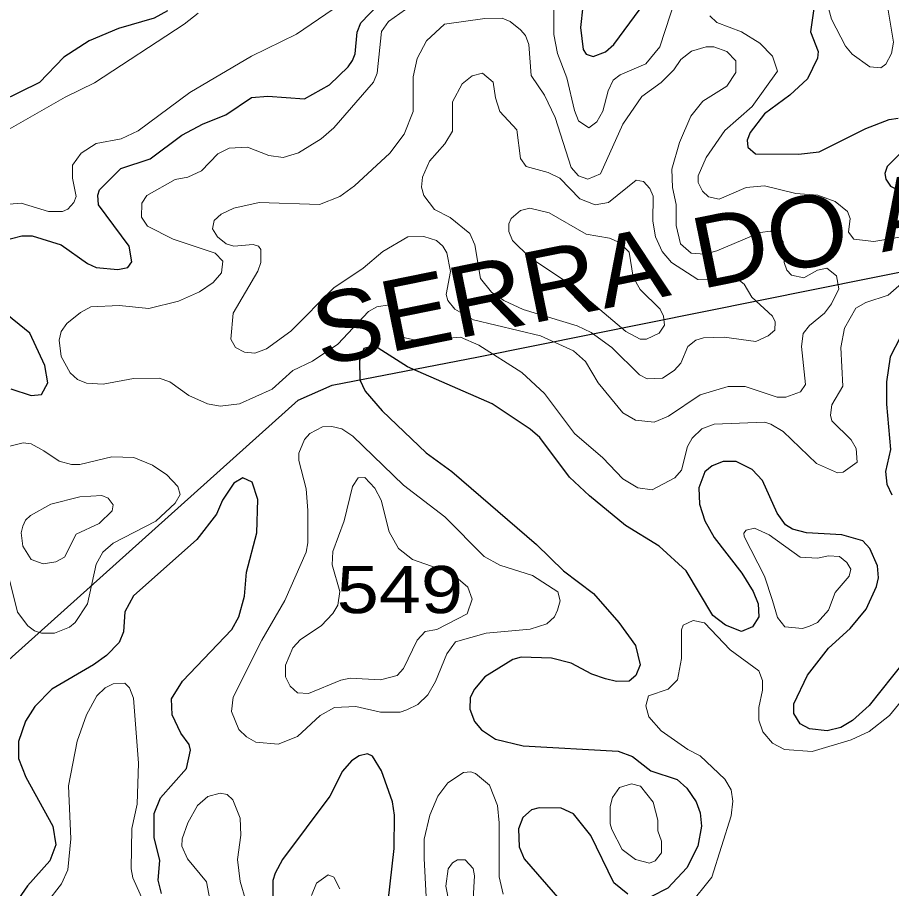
# Model space of a CAD drawing. Extents: x 577 to 602.9, y 7483.8 to 7511.6.
# Drawn here: x 597.148 to 598.63, y 7494.897 to 7496.373 of the extents above; entities that cross this region are included whole.
import ezdxf
from ezdxf.enums import TextEntityAlignment as Align

# ---------------------------------------------------------------- set-up
doc = ezdxf.new("R2010")
doc.units = 0
doc.header["$LTSCALE"] = 0.032
for name, color, linetype, lineweight in [('1', 7, 'Continuous', 25), ('2', 7, 'Continuous', 13), ('26', 7, 'Continuous', 25)]:
    doc.layers.add(name, color=color, linetype=linetype, lineweight=lineweight)
doc.layers.add('61', color=7, linetype='Continuous')

msp = doc.modelspace()

# ---------------------------------------------------------------- linework, layer by layer
at = {"layer": '1'}
for points in [[(598.1106, 7496.4294), (598.1026, 7496.3563), (598.1074, 7496.3189), (598.1122, 7496.311), (598.1241, 7496.307), (598.1448, 7496.3149), (598.1591, 7496.3277), (598.2036, 7496.3881)], [(597.1206, 7495.9945), (597.1556, 7496.0032), (597.1731, 7496.0032), (597.2224, 7495.9881), (597.2669, 7495.9563), (597.282, 7495.9499), (597.3186, 7495.946), (597.3353, 7495.9499), (597.3424, 7495.9595), (597.3377, 7495.9857), (597.286, 7496.0557), (597.2844, 7496.0724), (597.2876, 7496.0811), (597.3234, 7496.1177), (597.3735, 7496.1336), (597.4267, 7496.1742), (597.4633, 7496.1933), (597.5015, 7496.2084), (597.5452, 7496.2378), (597.573, 7496.2402), (597.6351, 7496.2354), (597.6772, 7496.2593), (597.709, 7496.2895), (597.7162, 7496.3006), (597.721, 7496.3117), (597.7241, 7496.3483), (597.7305, 7496.3642), (597.7758, 7496.4119)], [(598.4994, 7496.3968), (598.4923, 7496.3491), (598.5058, 7496.3157), (598.5042, 7496.3046), (598.4875, 7496.2696), (598.4573, 7496.2418), (598.4143, 7496.21), (598.3905, 7496.1782), (598.3849, 7496.1654), (598.3865, 7496.1535), (598.3992, 7496.1424), (598.4724, 7496.1416), (598.5074, 7496.1456), (598.5861, 7496.1853), (598.6259, 7496.2004), (598.641, 7496.2028)], [(597.4029, 7496.3849), (597.3798, 7496.3722), (597.3194, 7496.3547), (597.2701, 7496.334), (597.2271, 7496.3062), (597.1858, 7496.2632), (597.0864, 7496.2147)], [(598.6497, 7496.1479), (598.6227, 7496.1209), (598.6187, 7496.109), (598.6203, 7496.0994), (598.6282, 7496.0875), (598.6457, 7496.0788)], [(597.1373, 7495.744), (597.1715, 7495.7329), (597.189, 7495.7344), (597.2001, 7495.7543), (597.1945, 7495.7838), (597.1691, 7495.8386), (597.1214, 7495.8776)], [(598.6449, 7495.8323), (598.6275, 7495.7981), (598.6211, 7495.7559), (598.6211, 7495.7178), (598.6282, 7495.6414), (598.6195, 7495.604), (598.6219, 7495.5826), (598.6306, 7495.5643)], [(598.5209, 7495.1643), (598.4907, 7495.1675), (598.4748, 7495.1762), (598.4644, 7495.1937), (598.4644, 7495.2104), (598.4875, 7495.2589), (598.5233, 7495.3043), (598.5599, 7495.3377), (598.5869, 7495.3703), (598.6044, 7495.4092), (598.6076, 7495.4235), (598.606, 7495.4442), (598.5933, 7495.4736), (598.5813, 7495.4864), (598.5455, 7495.4967), (598.4859, 7495.4999), (598.4621, 7495.5062), (598.4501, 7495.5134), (598.4358, 7495.5333), (598.4112, 7495.5889), (598.3937, 7495.6072), (598.3666, 7495.6207), (598.3444, 7495.6207), (598.3261, 7495.6136), (598.3134, 7495.6032), (598.303, 7495.5762), (598.3046, 7495.5484), (598.3134, 7495.5205), (598.3293, 7495.4919), (598.3762, 7495.4315), (598.3953, 7495.4005), (598.404, 7495.3798), (598.4048, 7495.3575), (598.3945, 7495.3408), (598.3754, 7495.3329), (598.3483, 7495.3432), (598.3269, 7495.3599), (598.2816, 7495.4355), (598.2362, 7495.4776), (598.179, 7495.5126), (598.1177, 7495.5627), (598.0843, 7495.5945), (598.0335, 7495.6613), (598.0176, 7495.6756), (597.9531, 7495.7185), (597.8092, 7495.7814), (597.7599, 7495.8132), (597.7488, 7495.8156), (597.7353, 7495.8124), (597.7281, 7495.7917), (597.7289, 7495.7591), (597.7377, 7495.74), (597.7663, 7495.7066), (597.841, 7495.6358), (597.8848, 7495.604), (598.0279, 7495.48), (598.074, 7495.4355), (598.1249, 7495.3973), (598.1678, 7495.348), (598.1957, 7495.309), (598.2036, 7495.2764), (598.1965, 7495.2581), (598.1853, 7495.2486), (598.1639, 7495.2478), (598.1448, 7495.2526), (598.1217, 7495.2605), (598.0867, 7495.2788), (598.0533, 7495.2876), (598.0024, 7495.2892), (597.9881, 7495.2852), (597.9404, 7495.2558), (597.9229, 7495.2351), (597.9158, 7495.2208), (597.915, 7495.2009), (597.9229, 7495.1802), (597.9349, 7495.1659), (597.9587, 7495.15), (598.0056, 7495.1389), (598.1663, 7495.1301), (598.1909, 7495.1206), (598.2219, 7495.0967), (598.2664, 7495.0816), (598.2831, 7495.0673), (598.299, 7495.0442), (598.3054, 7495.0252), (598.3078, 7495.0029), (598.3014, 7494.9687), (598.2831, 7494.9321), (598.2505, 7494.8979), (598.2219, 7494.8828)], [(597.3925, 7494.8884), (597.387, 7494.9114), (597.3894, 7494.9448), (597.3798, 7494.9838), (597.3798, 7495.0244), (597.391, 7495.0506), (597.4347, 7495.1007), (597.4418, 7495.1317), (597.4395, 7495.1412), (597.4251, 7495.1603), (597.4108, 7495.1913), (597.4092, 7495.2184), (597.4283, 7495.2486), (597.5118, 7495.3361), (597.5237, 7495.3575), (597.5333, 7495.3925), (597.5365, 7495.4331), (597.554, 7495.4999), (597.5556, 7495.5563), (597.546, 7495.5858), (597.5301, 7495.5929), (597.515, 7495.5842), (597.4959, 7495.5555), (597.4856, 7495.5317), (597.4522, 7495.4887), (597.3448, 7495.3933), (597.3305, 7495.3663), (597.3281, 7495.3321), (597.321, 7495.3138), (597.2995, 7495.2923), (597.2772, 7495.2764), (597.2065, 7495.2351), (597.1778, 7495.2057), (597.1619, 7495.181), (597.15, 7495.146), (597.15, 7495.1174), (597.1627, 7495.0856), (597.2081, 7495.0029), (597.2136, 7494.9711), (597.2033, 7494.944), (597.1651, 7494.9019), (597.15, 7494.8796)], [(598.6712, 7495.3066), (598.5917, 7495.2072), (598.5638, 7495.1818), (598.544, 7495.1699), (598.5209, 7495.1643)], [(597.7734, 7494.8454), (597.787, 7494.9647), (597.7877, 7495.0212), (597.7838, 7495.0442), (597.7655, 7495.0967), (597.7504, 7495.1214), (597.7416, 7495.1253), (597.7273, 7495.1222), (597.7146, 7495.1134), (597.6995, 7495.0959), (597.678, 7495.0538), (597.5977, 7494.9464), (597.585, 7494.9234), (597.581, 7494.9106), (597.581, 7494.8749)], [(598.1829, 7494.8876), (598.1591, 7494.9067), (598.1201, 7494.987), (598.0907, 7495.0236), (598.07, 7495.0331), (598.0327, 7495.0339), (598.0199, 7495.0307), (598.0048, 7495.0172), (597.9977, 7494.9981), (597.9985, 7494.9679)], [(597.9985, 7494.9679), (598.0072, 7494.9472), (598.0676, 7494.878)]]:
    msp.add_lwpolyline(points, dxfattribs=at)
at = {"layer": '2'}
for points in [[(598.5145, 7496.4207), (598.5281, 7496.3706), (598.5519, 7496.3245), (598.563, 7496.311), (598.5933, 7496.2895), (598.6115, 7496.2879), (598.6203, 7496.2943), (598.6298, 7496.3125), (598.633, 7496.3316), (598.6243, 7496.3857)], [(598.0573, 7496.4048), (598.0573, 7496.3443), (598.0637, 7496.3125), (598.0796, 7496.2712), (598.0923, 7496.2155), (598.0995, 7496.198), (598.1169, 7496.1861), (598.1305, 7496.1964), (598.1408, 7496.2147), (598.1496, 7496.2489), (598.1583, 7496.2672), (598.1702, 7496.276), (598.2132, 7496.295), (598.237, 7496.3237), (598.2641, 7496.4072)], [(597.4832, 7495.9738), (597.4124, 7495.9977), (597.3687, 7496.0199), (597.3584, 7496.035), (597.3591, 7496.0589), (597.3679, 7496.0716), (597.4156, 7496.0986), (597.4371, 7496.1026), (597.4601, 7496.1137), (597.488, 7496.1424), (597.507, 7496.1519), (597.5381, 7496.1535), (597.5746, 7496.1392), (597.5985, 7496.136), (597.6247, 7496.144), (597.6629, 7496.1678), (597.6844, 7496.1861), (597.752, 7496.264), (597.7583, 7496.2791), (597.7655, 7496.3499), (597.7774, 7496.3666), (597.8156, 7496.3937)], [(597.4546, 7496.3809), (597.4307, 7496.3618), (597.2788, 7496.2624), (597.2295, 7496.2386), (597.1262, 7496.1797)], [(597.1278, 7496.0565), (597.1548, 7496.0589), (597.2009, 7496.0446), (597.2248, 7496.0446), (597.2335, 7496.0485), (597.2438, 7496.0597), (597.2478, 7496.07), (597.2415, 7496.101), (597.2415, 7496.1233), (597.2566, 7496.1432), (597.282, 7496.1599), (597.3242, 7496.1678), (597.3528, 7496.1813), (597.4403, 7496.2465), (597.5452, 7496.3078), (597.6216, 7496.3451), (597.6836, 7496.3873)], [(598.3221, 7496.3762), (598.334, 7496.365), (598.3754, 7496.3491), (598.4064, 7496.33), (598.4279, 7496.3078), (598.4366, 7496.2823), (598.3937, 7496.2227), (598.3476, 7496.1821), (598.3157, 7496.136), (598.3022, 7496.105), (598.3022, 7496.0939), (598.3094, 7496.0788), (598.3197, 7496.0692), (598.338, 7496.0652), (598.3833, 7496.0851), (598.4143, 7496.0883), (598.4676, 7496.0748), (598.505, 7496.0724), (598.5344, 7496.0613), (598.5551, 7496.0446), (598.5599, 7496.0326), (598.5567, 7496.0096), (598.5662, 7495.9977), (598.5996, 7495.9937), (598.6434, 7496.0008)], [(598.1368, 7496.1082), (598.1154, 7496.0994), (598.0995, 7496.105), (598.0867, 7496.1193), (598.0597, 7496.2036), (598.0414, 7496.2418), (598.0191, 7496.2752), (598.0152, 7496.3277), (598.0096, 7496.3428), (598.0009, 7496.3523), (597.9834, 7496.3666), (597.9698, 7496.3722), (597.9404, 7496.3714), (597.872, 7496.3618), (597.8418, 7496.334), (597.8259, 7496.3038), (597.8188, 7496.2728), (597.8188, 7496.2139), (597.8037, 7496.1758), (597.7798, 7496.1432), (597.7194, 7496.0883), (597.6947, 7496.07), (597.6605, 7496.0565), (597.5579, 7496.0597), (597.515, 7496.0501), (597.4935, 7496.0398), (597.4816, 7496.0295), (597.4792, 7496.0151), (597.4872, 7496.0016), (597.5023, 7495.9897), (597.515, 7495.9857), (597.5476, 7495.9889), (597.5571, 7495.9857), (597.5611, 7495.9802), (597.5611, 7495.9579), (597.5556, 7495.9436), (597.5142, 7495.872), (597.5102, 7495.8283), (597.5182, 7495.814), (597.5333, 7495.806), (597.5508, 7495.8044), (597.5707, 7495.8116), (597.612, 7495.8418), (597.6844, 7495.915), (597.7345, 7495.9484), (597.7679, 7495.977), (597.81, 7496.0016), (597.837, 7496.0024), (597.8585, 7495.9953), (597.8696, 7495.9857), (597.876, 7495.9746), (597.8824, 7495.9428), (597.8752, 7495.9038), (597.8776, 7495.8935), (597.8895, 7495.8792), (597.9213, 7495.8609), (598.035, 7495.8338), (598.0907, 7495.8084), (598.1114, 7495.7901), (598.1329, 7495.7543), (598.1742, 7495.7034), (598.1957, 7495.6907), (598.2275, 7495.6875), (598.2521, 7495.6979), (598.3054, 7495.7337), (598.3531, 7495.748), (598.3817, 7495.748), (598.4358, 7495.7297), (598.4509, 7495.7297), (598.4756, 7495.7392), (598.4843, 7495.7511), (598.4772, 7495.8156), (598.4803, 7495.8378), (598.4907, 7495.8513), (598.5161, 7495.872), (598.5281, 7495.8879), (598.5408, 7495.9134), (598.5368, 7495.9356), (598.5201, 7495.9484), (598.5042, 7495.9452), (598.4811, 7495.9324), (598.4605, 7495.9364), (598.4525, 7495.9452), (598.4477, 7495.9579), (598.4462, 7495.9929), (598.4382, 7496.0032), (598.4247, 7496.0112), (598.4072, 7496.0088), (598.334, 7495.9778), (598.3134, 7495.9722), (598.2903, 7495.9738), (598.272, 7495.9897), (598.2649, 7496.0207), (598.2649, 7496.0565), (598.2585, 7496.0851), (598.2577, 7496.1161), (598.2704, 7496.1615), (598.2895, 7496.206), (598.3102, 7496.2314), (598.3507, 7496.2569), (598.3658, 7496.2799)], [(598.3658, 7496.2799), (598.3658, 7496.2998), (598.3507, 7496.3157), (598.3285, 7496.3237), (598.3157, 7496.3237), (598.2911, 7496.3165), (598.2728, 7496.3022), (598.2609, 7496.2847), (598.2394, 7496.2632), (598.2068, 7496.2394), (598.1742, 7496.1925), (598.1368, 7496.1082)], [(598.5265, 7495.6995), (598.5289, 7495.6899), (598.5615, 7495.6573), (598.5702, 7495.643), (598.5718, 7495.6199), (598.5479, 7495.6025), (598.5384, 7495.6017), (598.5026, 7495.6176), (598.4462, 7495.6716), (598.4255, 7495.6844), (598.4151, 7495.6875), (598.3293, 7495.6844), (598.3086, 7495.6764), (598.2919, 7495.6605), (598.2839, 7495.6462), (598.2736, 7495.6064), (598.2625, 7495.5929), (598.2243, 7495.573), (598.1996, 7495.5762), (598.1742, 7495.5913), (598.1408, 7495.6271), (598.0923, 7495.6684), (598.0414, 7495.736), (598.0032, 7495.7718), (597.9301, 7495.8179), (597.8991, 7495.8315), (597.8283, 7495.8251), (597.8005, 7495.8315), (597.7877, 7495.8426), (597.787, 7495.8776), (597.7782, 7495.8863), (597.7575, 7495.8831), (597.7432, 7495.8752), (597.6915, 7495.8195), (597.6486, 7495.7909), (597.6152, 7495.775), (597.5802, 7495.7432), (597.5245, 7495.7185), (597.4919, 7495.7146), (597.4705, 7495.7185), (597.4387, 7495.7329), (597.4069, 7495.7559), (597.3886, 7495.7623), (597.3448, 7495.7615), (597.2939, 7495.7519), (597.2653, 7495.7535), (597.2502, 7495.7599), (597.2375, 7495.771), (597.2224, 7495.7989), (597.2192, 7495.8267), (597.2224, 7495.841), (597.2319, 7495.8545), (597.255, 7495.8736), (597.2725, 7495.8831), (597.321, 7495.8855), (597.3711, 7495.88), (597.4212, 7495.8927), (597.457, 7495.9086), (597.48, 7495.9245), (597.4943, 7495.9404), (597.4967, 7495.9603), (597.4832, 7495.9738)], [(598.6656, 7495.9388), (598.6243, 7495.903), (598.5861, 7495.8903), (598.5694, 7495.8808), (598.5503, 7495.8466), (598.544, 7495.814), (598.5471, 7495.7488), (598.5289, 7495.717), (598.5265, 7495.6995)], [(597.1357, 7495.647), (597.158, 7495.6525), (597.1715, 7495.651), (597.193, 7495.639), (597.2192, 7495.6215), (597.2399, 7495.616), (597.2542, 7495.616), (597.3083, 7495.6287), (597.3456, 7495.6279), (597.3774, 7495.6144), (597.4013, 7495.5985), (597.4204, 7495.5786), (597.4244, 7495.5651), (597.4156, 7495.55), (597.383, 7495.5198), (597.3106, 7495.4824), (597.2931, 7495.4673), (597.282, 7495.4466), (597.2669, 7495.3798), (597.2462, 7495.348), (597.2367, 7495.34), (597.2112, 7495.3297), (597.189, 7495.3297), (597.1771, 7495.3337), (597.1659, 7495.3424), (597.1484, 7495.3655), (597.1341, 7495.4227)], [(598.6672, 7495.2398), (598.6267, 7495.1905), (598.5917, 7495.1635), (598.5615, 7495.1492), (598.4955, 7495.1293), (598.4485, 7495.1325), (598.4279, 7495.1436), (598.412, 7495.1627), (598.4048, 7495.1826), (598.4048, 7495.2041), (598.4112, 7495.2335), (598.4112, 7495.2494), (598.4048, 7495.2661), (598.3563, 7495.3019), (598.3126, 7495.3472), (598.2935, 7495.3512), (598.2768, 7495.3432), (598.2736, 7495.3353), (598.2736, 7495.2868), (598.2672, 7495.251), (598.2513, 7495.2351), (598.2179, 7495.2239), (598.2132, 7495.2065), (598.2187, 7495.1882), (598.2394, 7495.1643), (598.2847, 7495.1325), (598.3054, 7495.1222), (598.3476, 7495.0824), (598.3579, 7495.0641), (598.3611, 7495.045), (598.3579, 7495.0204), (598.3253, 7494.9162), (598.2863, 7494.8677)], [(597.3687, 7494.8598), (597.344, 7494.9154), (597.3409, 7494.9305), (597.3424, 7494.9989), (597.3512, 7495.0403), (597.3536, 7495.1094), (597.3448, 7495.22), (597.3385, 7495.2375), (597.3305, 7495.2454), (597.3106, 7495.2438), (597.2971, 7495.2375), (597.2828, 7495.2239), (597.2653, 7495.1913), (597.2494, 7495.1468), (597.2351, 7495.0713), (597.2391, 7494.9814), (597.2335, 7494.9289), (597.2232, 7494.9051), (597.1977, 7494.8725)], [(597.841, 7494.8828), (597.8378, 7494.948), (597.8378, 7494.9806), (597.8474, 7495.0212), (597.8609, 7495.0538), (597.8776, 7495.076), (597.9046, 7495.0935), (597.9166, 7495.0951), (597.9245, 7495.0919), (597.9484, 7495.0721), (597.9619, 7495.0379), (597.9651, 7495.0085), (597.9651, 7494.917), (597.9714, 7494.8876)], [(597.6947, 7494.8963), (597.6844, 7494.9162), (597.6748, 7494.9202), (597.655, 7494.9059), (597.647, 7494.8852)]]:
    msp.add_lwpolyline(points, dxfattribs=at)
for points in [[(597.9587, 7496.237), (597.9659, 7496.2139), (597.9945, 7496.1829), (598.0009, 7496.1344), (598.0104, 7496.1209), (598.0478, 7496.1106), (598.0676, 7496.101), (598.1018, 7496.066), (598.1273, 7496.0557), (598.1503, 7496.0597), (598.1973, 7496.0978), (598.2092, 7496.0955), (598.2203, 7496.0835), (598.2259, 7496.0708), (598.2251, 7496.0279), (598.2299, 7496.0016), (598.241, 7495.977), (598.2569, 7495.9579), (598.3014, 7495.9293), (598.3722, 7495.9277), (598.3802, 7495.9213), (598.3929, 7495.8991), (598.4279, 7495.8672), (598.4326, 7495.8577), (598.4318, 7495.8434), (598.4207, 7495.8338), (598.4, 7495.8243), (598.346, 7495.8315), (598.311, 7495.8307), (598.2982, 7495.8267), (598.2847, 7495.8156), (598.2728, 7495.7877), (598.2617, 7495.775), (598.2418, 7495.7623), (598.2156, 7495.7607), (598.2028, 7495.7678), (598.1559, 7495.814), (598.1209, 7495.8394), (598.0971, 7495.8505), (598.0056, 7495.8784), (597.973, 7495.8935), (597.9516, 7495.9078), (597.9333, 7495.9309), (597.9237, 7495.9881), (597.915, 7496.0072), (597.8816, 7496.0342), (597.8553, 7496.0477), (597.837, 7496.0716), (597.8331, 7496.0859), (597.8347, 7496.1026), (597.8466, 7496.1297), (597.8728, 7496.1591), (597.8856, 7496.1805), (597.8856, 7496.2306), (597.9023, 7496.2609), (597.919, 7496.2744), (597.9364, 7496.2791), (597.9547, 7496.264)], [(598.2036, 7495.9126), (598.2378, 7495.8792), (598.2434, 7495.8672), (598.245, 7495.8521), (598.2362, 7495.8386), (598.2148, 7495.8283), (598.2036, 7495.8283), (598.1798, 7495.841), (598.0843, 7495.9221), (598.0168, 7495.9666), (597.9873, 7495.9953), (597.981, 7496.0104), (597.981, 7496.0239), (597.985, 7496.0326), (598.0009, 7496.0462), (598.0168, 7496.0501), (598.0494, 7496.0422), (598.1122, 7496.0064), (598.1519, 7495.9992), (598.1686, 7495.9921), (598.1853, 7495.9754), (598.1917, 7495.9332)], [(597.9428, 7495.3297), (598.0176, 7495.3369), (598.0454, 7495.3456), (598.0589, 7495.3575), (598.0637, 7495.3687), (598.0684, 7495.3846), (598.0645, 7495.3997), (598.0215, 7495.4275), (597.9659, 7495.445), (597.9396, 7495.4601), (597.8728, 7495.5269), (597.8029, 7495.581), (597.717, 7495.6637), (597.6979, 7495.6764), (597.6812, 7495.6804), (597.6653, 7495.6796), (597.6438, 7495.6684), (597.6351, 7495.6581), (597.6255, 7495.6351), (597.6255, 7495.6223), (597.6375, 7495.5746), (597.6406, 7495.538), (597.6406, 7495.4832), (597.6375, 7495.4673), (597.6017, 7495.3854), (597.5627, 7495.3178), (597.5142, 7495.2216), (597.511, 7495.1969), (597.5237, 7495.1667), (597.5365, 7495.154), (597.5524, 7495.1452), (597.5905, 7495.142), (597.6231, 7495.1548), (597.6613, 7495.1905), (597.686, 7495.2041), (597.7217, 7495.2057), (597.7639, 7495.1961), (597.7973, 7495.1961), (597.8084, 7495.2001), (597.8267, 7495.2088), (597.8442, 7495.2255), (597.8569, 7495.2478), (597.876, 7495.2947), (597.8911, 7495.3154)], [(597.8954, 7495.4217), (597.8712, 7495.4363), (597.818, 7495.4545), (597.7941, 7495.4736), (597.7782, 7495.5015), (597.7647, 7495.5555), (597.7543, 7495.5754), (597.7369, 7495.5937), (597.7257, 7495.5929), (597.7162, 7495.5786), (597.7019, 7495.5205), (597.6828, 7495.4681), (597.682, 7495.4458), (597.6947, 7495.4005), (597.6915, 7495.3774), (597.6828, 7495.3631), (597.6629, 7495.3424), (597.6279, 7495.3194), (597.6152, 7495.3051), (597.6025, 7495.2756), (597.6025, 7495.2558), (597.6104, 7495.2398), (597.6231, 7495.2287), (597.6414, 7495.2279), (597.6963, 7495.2502), (597.7122, 7495.2534), (597.7639, 7495.251), (597.7917, 7495.2581), (597.8029, 7495.2701), (597.8259, 7495.3178), (597.8394, 7495.3329), (597.8593, 7495.3361), (597.9107, 7495.3629), (597.9191, 7495.3874), (597.9116, 7495.4078)], [(597.1707, 7495.5293), (597.2049, 7495.5484), (597.2542, 7495.5611), (597.2916, 7495.5635), (597.3019, 7495.5587), (597.3106, 7495.5476), (597.3091, 7495.5372), (597.2868, 7495.5158), (597.2478, 7495.4975), (597.2279, 7495.4585), (597.2136, 7495.4506), (597.1922, 7495.4474), (597.1715, 7495.4545), (597.1572, 7495.4776), (597.1548, 7495.4999), (597.1572, 7495.511), (597.1619, 7495.5213)], [(598.4279, 7495.3854), (598.4366, 7495.3567), (598.4493, 7495.3408), (598.4788, 7495.3377), (598.4907, 7495.3416), (598.5042, 7495.348), (598.5233, 7495.3687), (598.5344, 7495.3989), (598.5583, 7495.4267), (598.5607, 7495.4386), (598.5543, 7495.4498), (598.5416, 7495.4601), (598.5233, 7495.4609), (598.5042, 7495.4569), (598.4748, 7495.4585), (598.4223, 7495.4967), (598.3976, 7495.5078), (598.3833, 7495.5046), (598.3794, 7495.4991), (598.3802, 7495.4935), (598.4143, 7495.4267)], [(598.1559, 7494.9973), (598.1734, 7494.9631), (598.1957, 7494.9464), (598.2195, 7494.9401), (598.2291, 7494.944), (598.2402, 7494.9576), (598.2402, 7494.9774), (598.2338, 7494.9949), (598.2338, 7495.0132), (598.2259, 7495.0434), (598.2044, 7495.0705), (598.1893, 7495.0745), (598.1686, 7495.0681), (598.1567, 7495.0514), (598.1527, 7495.0363), (598.1527, 7495.0069)], [(597.4919, 7495.0585), (597.5039, 7495.0562), (597.5134, 7495.0474), (597.5261, 7495.0164), (597.5269, 7494.9878), (597.5214, 7494.9464), (597.5261, 7494.9091), (597.5357, 7494.8765), (597.5357, 7494.8566), (597.5301, 7494.8399), (597.515, 7494.8279), (597.4927, 7494.8327), (597.4856, 7494.8407), (597.476, 7494.8693), (597.4689, 7494.9083), (597.4363, 7494.9472), (597.4267, 7494.9687), (597.4275, 7494.9814), (597.4371, 7495.0085), (597.4538, 7495.0379), (597.4713, 7495.053)], [(597.8856, 7494.9409), (597.8943, 7494.9456), (597.907, 7494.9456), (597.9205, 7494.9313), (597.9229, 7494.9186), (597.9205, 7494.8796), (597.9388, 7494.816), (597.9555, 7494.7731), (597.9555, 7494.7468), (597.9237, 7494.6816), (597.9134, 7494.6482), (597.903, 7494.6292), (597.8776, 7494.5966), (597.8498, 7494.5743), (597.8378, 7494.5775), (597.8307, 7494.5846), (597.8291, 7494.6093), (597.849, 7494.6459), (597.8768, 7494.68), (597.8951, 7494.7158), (597.8959, 7494.7914), (597.8744, 7494.9011), (597.8784, 7494.9305)]]:
    msp.add_lwpolyline(points, close=True, dxfattribs=at)
at = {"layer": '26'}
msp.add_lwpolyline([(596.3235, 7494.8199), (596.4766, 7494.8992), (596.554, 7494.9298), (596.7174, 7494.964), (596.8084, 7494.9933), (597.6244, 7495.7246), (597.6816, 7495.7502), (597.9299, 7495.7984), (599.0697, 7496.0277), (599.1695, 7496.044), (599.3435, 7496.0707), (599.4306, 7496.0881), (599.5907, 7496.1124), (599.6743, 7496.1101), (599.8741, 7496.052), (600.0689, 7495.9566), (600.1375, 7495.9162), (600.3027, 7495.8544), (600.3968, 7495.841), (600.5616, 7495.8366), (600.6496, 7495.8454)], dxfattribs=at)

# ---------------------------------------------------------------- texts
at = {"layer": '26', "width": 1.1}
msp.add_text('SERRA DO ARROZAL', height=0.12, rotation=11.483, dxfattribs=at).set_placement((598.5465, 7495.9615), align=Align.CENTER)
at = {"layer": '61', "width": 1.2}
msp.add_text('549', height=0.08, dxfattribs=at).set_placement((597.7965, 7495.3638), align=Align.CENTER)

doc.saveas('drawing.dxf')
